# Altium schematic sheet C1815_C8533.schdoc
size 127 x 101 mm
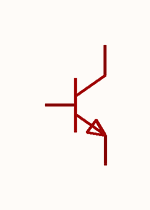
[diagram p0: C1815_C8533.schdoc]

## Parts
Q?  c1815(range:200-400)  [SOT-23-3_L2.9-W1.3-P1.90-LS2.4-BR]  (value not drawn)

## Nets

Not connected (* = marked no-connect by the designer): Q? 1(B) 2(E) 3(C)

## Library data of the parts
Q? = c1815(range:200-400): 晶体管类型:NPN;集电极电流(Ic):150mA;集射极击穿电压(Vceo):50V;耗散功率(Pd):200mW;直流电流增益(hFE):200;; Manufacturer: CJ(江苏长电/长晶); Symbol: C1815_C8533; AddInBom: yes; ModelId: c62791f0466c4ae2a892c056b845b0ca; ModelName: SOT-23-3P_L2.9-W1.3-H1.0-LS2.4-P0.95; ModelTransform: 98.425,114.173,0,180,0,0,0.0005,-0.0005,0; type: NPN; Current - Collector(Ic): 150mA; Collector - Emitter Voltage VCEO: 50V; Pd - Power Dissipation: 200mW; DC Current Gain: 200; Transition frequency(fT): 80MHz; Current - Collector Cutoff: 100nA; Vce Saturation(VCE(sat)): 250mV; Emitter-Base Voltage(Vebo): 5V; Number: 1个NPN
